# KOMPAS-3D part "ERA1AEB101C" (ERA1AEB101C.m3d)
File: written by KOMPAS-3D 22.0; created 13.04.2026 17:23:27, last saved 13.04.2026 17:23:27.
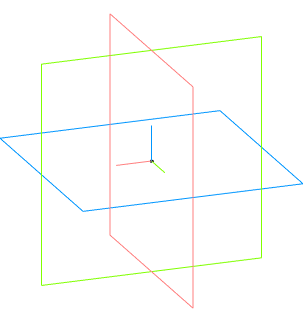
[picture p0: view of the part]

Document properties: Автор: Andrey; Полное имя файла: C:\Users\User1\Documents\ERA1AEB101C.m3d

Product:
- Part/product: ERA1AEB101C

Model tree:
1. Операция без истории:1
2. Операция без истории:2
3. Операция без истории:3
4. Операция без истории:4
